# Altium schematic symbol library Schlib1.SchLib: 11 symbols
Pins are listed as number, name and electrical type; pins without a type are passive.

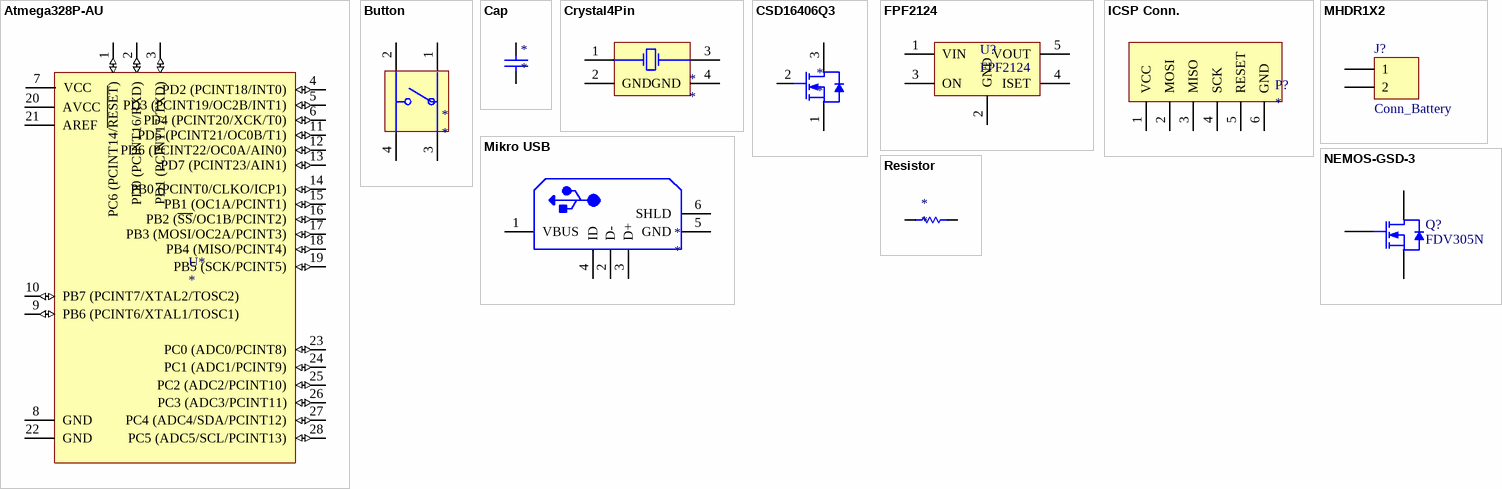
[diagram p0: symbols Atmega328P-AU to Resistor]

## Atmega328P-AU
designator U*
pins: 1 PC6 (PCINT14/~{RESET}) (io), 2 PD0 (PCINT16/RXD) (io), 3 PD1 (PCINT17/TXD) (io), 4 PD2 (PCINT18/INT0) (io), 5 PD3 (PCINT19/OC2B/INT1) (io), 6 PD4 (PCINT20/XCK/T0) (io), 7 VCC (power), 8 GND (power), 9 PB6 (PCINT6/XTAL1/TOSC1) (io), 10 PB7 (PCINT7/XTAL2/TOSC2) (io), 11 PD5 (PCINT21/OC0B/T1) (io), 12 PD6 (PCINT22/OC0A/AIN0) (io), 13 PD7 (PCINT23/AIN1) (io), 14 PB0 (PCINT0/CLKO/ICP1) (io), 15 PB1 (OC1A/PCINT1) (io), 16 PB2 (~{SS}/OC1B/PCINT2) (io), 17 PB3 (MOSI/OC2A/PCINT3) (io), 18 PB4 (MISO/PCINT4) (io), 19 PB5 (SCK/PCINT5) (io), 20 AVCC (power), 21 AREF (power), 22 GND (power), 23 PC0 (ADC0/PCINT8) (io), 24 PC1 (ADC1/PCINT9) (io), 25 PC2 (ADC2/PCINT10) (io), 26 PC3 (ADC3/PCINT11) (io), 27 PC4 (ADC4/SDA/PCINT12) (io), 28 PC5 (ADC5/SCL/PCINT13) (io)

## Button
designator *
pins: 1 A, 2 B, 3 A', 4 B'

## Cap
designator *
footprint Cap
pins: 1, 2

## Crystal4Pin
designator *
pins: 1 X1, 2 GND (power), 3 X2, 4 GND (power)

## CSD16406Q3
designator *
pins: 1 S, 2 G, 3 D

## FPF2124
designator U?
footprint SOT23-5
pins: 1 VIN, 2 GND, 3 ON, 4 ISET, 5 VOUT

## ICSP Conn.
designator P?
pins: 1 VCC, 2 MOSI, 3 MISO, 4 SCK, 5 RESET, 6 GND

## MHDR1X2
designator J?, comment Conn_Battery
Header, 2-Pin
footprint MHDR1X2 (Connector; Header; 2 Position)
signal-integrity model Connector
pins: 1, 2

## Mikro USB
designator *
pins: 1 VBUS, 2 D-, 3 D+, 4 ID, 5 GND, 6 SHLD

## NEMOS-GSD-3
designator Q?, comment FDV305N
N-Channel PowerTrench(R) MOSFET, 20 V, 0.9 A, -55 to 150 degC, 3-Pin SOT23, RoHS, Tape and Reel; Manufacturer: Fairchild Semiconductor
footprint FAIR-SOT23-3_V (SOT23, 3-Leads, Body 3.12x1.5mm, Pitch 0.95mm)
pins: 1 G, 2 S, 3 D

## Resistor
designator *
pins: 1, 2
